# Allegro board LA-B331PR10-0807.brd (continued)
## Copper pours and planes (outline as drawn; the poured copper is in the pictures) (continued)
GND on BOTTOM: 218.68,17.65 222.18,17.65 222.57,18.03 224.32,18.03 224.47,17.87 224.47,15.89 224.17,15.59 222.57,15.59 221.5,14.52 218.48,14.52 218.17,14.83 216.47,14.83 216.32,14.98 216.32,16.35 216.47,16.5 218.45,16.5 218.53,16.58 218.53,17.49
GND on BOTTOM: 193.84,23.13 190.66,23.13 190.41,23.39 190.41,24.48 190.16,24.73 187.49,24.73 187.36,24.86 187.36,26.26 187.23,26.38 183.3,26.38 183.04,26.64 183.04,27.27 183.3,27.53 185.08,27.53 185.2,27.65 185.2,28.92 185.46,29.18 187.49,29.18 187.62,29.05 193.2,29.05 194.35,27.91 194.35,23.64
GND on BOTTOM: 195.84,37.51 193.91,37.51 193.79,37.38 193.79,34.54 193.89,34.43 196.86,34.43 197.19,34.76 197.19,36.16
GND on BOTTOM: 244.05,35.7 244.05,36.24 243.9,36.39 243.22,36.39 243.06,36.24 243.06,35.1 243.22,34.94 243.98,34.94 244.05,35.02 244.05,35.55 244.51,35.55 244.51,35.7
GND on BOTTOM: 235.75,42.88 227.06,42.88 226.68,42.5 226.68,37.09 226.76,37 235.67,37 235.98,37.31 235.98,42.65
GND on BOTTOM: 219.52,31.97 218.37,31.97 218.22,31.82 218.22,31.36 218.6,30.98 218.6,29.84 218.68,29.76 219.52,29.76 219.59,29.84 219.59,31.89
GND on BOTTOM: 216.24,28.31 213.42,28.31 213.35,28.24 213.35,27.25 213.57,27.02 216.32,27.02 216.39,27.09 216.39,28.16
GND on BOTTOM: 278.42,27.48 277.58,28.31 276.9,28.31 276.74,28.16 276.74,27.09 276.9,26.94 276.9,24.05 276.67,23.82 275.33,23.82 275.15,23.64 275.15,20.29 275.28,20.16 276.97,20.16 277.11,20.3 277.11,23.02 277.41,23.31 277.41,23.31 277.98,23.88 277.98,25.49 278.32,25.83 279.69,25.83 280.02,25.49 280.02,24.88 280.55,24.88 280.63,24.96 280.63,25.95 280.55,26.03 279.94,26.03 279.79,26.18 279.79,27.25 279.56,27.48
GND on BOTTOM: 218.53,27.78 218.53,28.69 218.45,28.77 218.37,28.77 218.3,28.69 218.3,27.7 218.37,27.63 218.37,26.03 218.45,25.95 218.68,25.95 218.76,25.87 218.76,24.88 218.83,24.81 218.91,24.81 218.98,24.88 218.98,25.8 219.06,25.87 220.05,25.87 220.13,25.95 220.13,27.55 220.05,27.63 219.44,27.63 219.37,27.7 219.37,28.62 219.29,28.69 219.21,28.69 219.14,28.62 219.14,27.7 219.06,27.63 218.68,27.63
GND on BOTTOM: 271.79,47.33 269.43,47.33 269.35,47.25 269.35,42.75 269.02,42.42 269.02,36.46 269.46,36.02 271.01,36.02 271.26,36.27 271.26,43.32 271.3,43.36 271.3,43.9 271.94,44.54 271.94,47.17
GND on BOTTOM: 209.68,33.27 209.56,33.15 209.56,30.44 209.63,30.37 212.61,30.37 212.85,30.61 212.85,33.12 212.71,33.27
GND on GND1: outline of 113 points within 0.25,0.25 312.25,104.25 ; 1 cut-out
GND on IN1: 142.66,11.51 142.54,11.63 142.54,11.85 142.1,12.29 141.38,12.29 140.96,11.86 139.29,11.86 138.17,12.98 138.17,14.93 137.89,15.21 138.38,15.21 138.38,13.06 139.03,12.41 152.35,12.41 153.02,13.07 153.02,13.38 153.03,13.39 153.03,20.43 152.36,21.1 150.46,21.1 150.38,21.17 150.38,21.65 150.41,21.68 150.67,21.68 150.83,21.51 151.14,21.51 151.33,21.71 151.73,21.71 151.98,21.45 152.08,21.45 152.09,21.46 152.88,21.46 153.55,20.78 153.55,18.33 153.82,18.07 153.82,17.15 154.17,16.8 154.17,16.11 154.34,15.94 154.34,15.74 153.9,15.3 153.9,14.76 154.15,14.51 154.15,14.05 153.67,13.57 153.67,13.42 153.67,13.42 153.67,12.94 152.35,11.63 151.13,11.63 150.64,12.11 149.4,12.11 149.39,12.1 145.12,12.1 144.89,12.32 144.57,12.32 144.51,12.26 144.51,11.78 144.34,11.61 143.79,11.61 143.55,11.86 143.55,12.11 143.47,12.2 143.1,12.2 142.92,12.02 142.92,11.65 142.78,11.51 ; 1 cut-out
GND on IN1: 137.79,15.52 137.79,19.23 137.53,19.49 137.53,20.86 138.3,21.63 141.1,21.63 141.17,21.56 141.17,21.17 141.1,21.1 139.04,21.1 138.38,20.44 138.38,15.52
GND on VCC: 180.61,13.17 180.12,13.66 180.12,26.74 179.21,27.65 177.6,27.65 177.38,27.74 177.16,27.65 169.22,27.65 167.3,25.73 167.3,22.68 159.95,15.33 153.56,15.33 153.01,15.88 153.01,19.99 152.96,20.3 152.83,20.59 152.83,21.05 152.2,21.05 152.06,21.08 151.91,21.09 139.49,21.09 139.34,21.08 139.19,21.05 138.4,21.05 138.4,20.84 137.94,21.3 134.25,21.3 133.39,22.17 133.39,25.09 131.1,27.38 131.1,28.01 129.81,29.3 110,29.3 103.39,35.91 96.92,35.91 95.14,37.69 87.39,37.69 85.36,39.72 71.39,39.72 69.25,41.86 69.25,59.23 209.23,59.23 209.23,58.64 209.23,58.64 209.23,58.5 209.89,56.89 211.5,56.23 246.23,56.23 246.23,54 246.23,52.81 246.23,51.5 246.89,49.89 248.5,49.23 275.5,49.23 277.11,49.89 277.77,51.5 277.77,52.81 277.77,52.81 277.77,103.23 308.56,103.23 308.56,103.23 309.23,103.23 309.23,91.5 309.8,89.99 311.23,89.25 311.23,88.21 311.23,85.77 303.5,85.77 301.89,85.11 301.23,83.5 301.23,36.67 290.89,36.67 287.59,33.37 226.75,33.37 206.56,13.17 ; 1 cut-out
GND on IN2: 142.44,12.39 152.44,12.39 153.04,12.99 153.04,14.49 153.19,14.64 153.8,14.64 153.91,14.53 153.91,10.94 153.34,10.36 145.82,10.36 144.85,11.34 142.48,11.34 142.32,11.49 142.32,12.28
GND on IN2: 153.21,19.3 153.52,19.3 153.61,19.21 153.61,18.39 153.89,18.12 153.89,17.13 154.2,16.82 154.2,15.55 154.02,15.36 153.5,15.36 153.16,15.71 153.16,19.25
GND on IN2: 138.73,21.29 137.99,21.29 137.54,20.85 137.54,19.74 137.63,19.65 138.23,19.65 138.36,19.78 138.36,20.45 138.85,20.94 138.85,21.17
GND on IN3: 153.11,19.27 153.87,19.27 153.96,19.17 153.96,17.58 153.66,17.28 153.07,17.28 153.03,17.32 153.03,19.18
GND on IN3: 138.47,21.3 138.76,21.3 138.89,21.18 138.89,20.95 138.36,20.43 138.36,19.84 138.22,19.69 137.63,19.69 137.56,19.77 137.56,20.47 137.74,20.65 138.2,20.65 138.36,20.8 138.36,21.19
GND on GND2: outline of 115 points within 0.25,0.25 312.25,104.25 ; 1 cut-out
GND on IN4: 137.62,18.37 138.25,18.37 138.36,18.26 138.36,13.11 138.29,13.04 137.86,13.04 137.8,13.09 137.8,13.44 138.13,13.77 138.13,14.54 137.58,15.09 137.58,18.33
GND on IN4: 141.49,12.4 141.57,12.32 141.57,11.9 141.48,11.81 139.61,11.81 139.37,12.05 139.37,12.36 139.41,12.4
GND on IN4: 148.45,12.09 150.79,12.09 151.41,11.46 151.67,11.46 151.74,11.53 151.74,11.7 151.87,11.84 152.62,11.84 152.94,12.16 152.94,12.58 154.52,14.16 154.52,14.63 154.45,14.7 154.1,14.7 154,14.81 154,15.35 154.18,15.54 154.18,16.89 153.85,17.22 153.85,18.35 153.61,18.59 153.61,19.09 153.74,19.22 153.74,19.42 153.65,19.51 153.42,19.51 153.34,19.59 153.34,20.6 152.24,21.7 150.46,21.7 150.37,21.61 150.37,21.17 150.43,21.1 152.35,21.1 153.02,20.43 153.02,13.06 152.36,12.41 148.43,12.41 148.36,12.34 148.36,12.17
GND on GND3: outline of 116 points within 0.25,0.25 312.25,104.25 ; 2 cut-outs
GNDA_CHG on BOTTOM: 244.24,36.24 244.17,36.16 244.17,35.7 244.7,35.7 244.7,35.1 244.17,35.1 244.17,34.73 244.26,34.64 246.04,34.64 246.16,34.76 246.16,36.16 246.09,36.24
GNDA_CHG on IN4: 253.27,38.98 253.27,35.55 252.89,35.17 251.83,35.17 250.61,33.95 250.61,31.89 251.06,31.44 252.59,31.44 253.05,30.98 253.05,28.92 252.74,28.62 250.45,28.62 249.16,27.32 249.16,26.64 249.01,26.48 248.24,26.48 248.02,26.71 248.02,28.47 248.47,28.92 249.46,28.92 250.15,29.61 250.15,30.45 249.85,30.75 247.56,30.75 245.88,29.08 243.22,29.08 242.99,29.3 242.99,31.06 243.06,31.13 244.36,31.13 245.27,32.05 246.95,32.05 247.33,32.43 247.33,34.56 247.1,34.79 245.78,34.79 245.65,34.92 245.65,36.15 245.78,36.28 247.37,36.28 247.79,35.86 250.99,35.86 251.48,36.35 252.63,36.35 252.74,36.47 252.74,37.61 252.51,37.84 252.51,38.91 252.66,39.06 253.2,39.06
VBATT on BOTTOM: 251.45,47.29 251.2,47.04 251.2,43.65 251.44,43.41 256.73,43.41 257.11,43.79 257.11,47.12 256.94,47.29
VDD_1.35V on BOTTOM: 220.13,25.72 219.97,25.72 219.9,25.65 219.9,24.66 220.97,23.59 220.97,22.83 221.04,22.75 223.25,22.75 223.33,22.83 223.33,23.51 223.18,23.67 221.65,23.67 220.13,25.19
+DC_IN on BOTTOM: 255.1,20.24 255.03,20.16 253.27,20.16 252.39,21.05 252.39,22.58 252.5,22.7 253.39,22.7 253.89,23.2 255,23.2 255.1,23.1
+DC_IN on BOTTOM: 280.35,13.21 280.3,13.16 278.14,13.16 278.13,13.17 277.74,13.17 277.57,13.34 277.57,15.83 277.95,16.21 280.26,16.21 280.35,16.13
+DC_IN on BOTTOM: 276.56,6.22 276.67,6.33 276.67,6.88 276.38,7.17 276.38,9.02 276.29,9.11 269.43,9.11 269.12,8.81 269.12,6.53 269.44,6.22
+DC_IN on VCC: 269.13,6.57 268.9,6.8 268.9,17.22 267.73,18.38 253.71,18.38 252.64,19.45 252.64,22.09 253.12,22.57 254.05,22.57 254.18,22.45 272.09,22.45 278.31,16.23 279.7,16.23 279.82,16.11 279.82,11.76 277.28,9.22 277.28,6.68 277.17,6.57
+DCIN on BOTTOM: 250.91,32.05 252.59,32.05 252.97,31.67 255.18,31.67 255.41,31.89 255.41,32.96 255.48,33.04 257.16,33.04 257.24,32.96 257.24,30.98 256.93,30.68 252.74,30.68 251.6,31.82 250.91,31.82 250.84,31.89 250.84,31.97
+INV_PWR_SRC on BOTTOM (solid shape): 263.9,9.54 263.9,8.35 263.85,8.3 262.19,8.3 262.15,8.34 262.15,9.61 262.27,9.72 263.73,9.72
+INV_PWR_SRC on BOTTOM: 242.3,10.54 242.3,9.48 242.85,8.93 243.66,8.93 243.9,9.17 243.9,12.09 244.74,12.93 244.74,13.7 244.65,13.78 244.05,13.78 243.98,13.86 243.98,16.24 243.8,16.41 242.2,16.41 241.84,16.05 241.84,11
+INV_PWR_SRC on IN4: 261.97,9.17 263.35,9.17 263.46,9.06 263.46,7.66 263.26,7.46 242.91,7.46 241.81,8.56 241.81,10.62 242.12,10.94 243.85,10.94 244.1,10.69 244.1,9.97 245.21,8.87 261.82,8.87 261.97,9.02
+LCDVDD on BOTTOM: 256.32,9.62 255.69,9.62 255.56,9.49 255.56,8.35 255.69,8.22 256.32,8.22 256.45,8.35 256.45,9.49
+LCDVDD on BOTTOM: 254.67,12.16 254.8,12.03 256.59,12.03 256.83,12.27 256.83,13.04 255.94,13.92 255.94,15.46 255.81,15.59 255.81,16.28 256.56,17.02 256.56,18.74 256.43,18.86 255.15,18.86 255.12,18.84 255.12,17.41 254.67,16.97
+PBATT on BOTTOM: 247.41,47.44 243.81,47.44 243.61,47.23 243.61,43.59 243.42,43.4 242.83,43.4 242.68,43.25 242.68,42.41 242.76,42.33 245.65,42.33 245.73,42.41 245.73,43.4 246.04,43.71 247.41,43.71 247.71,44.01 247.71,47.13
+PWR_SRC_AC on BOTTOM: 263.64,22.45 261.88,22.45 261.73,22.29 261.73,20.46 261.96,20.24 263.79,20.24 264.09,19.93 264.09,19.63 263.87,19.4 262.04,19.4 261.88,19.25 261.88,18.71 262.04,18.56 262.79,18.56 263.09,18.25 265.12,18.25 265.22,18.36 265.22,19.13 265.01,19.34 265.01,21.53 264.86,21.68 263.94,21.68 263.79,21.84 263.79,22.29
+SDC_IN on BOTTOM: 258.15,22.06 257.39,22.06 257.31,21.99 257.31,18.79 257.47,18.64 261.28,18.64 261.35,18.71 261.35,19.4 261.28,19.47 259.75,19.47 259.52,19.7 259.52,20.08 259.67,20.24 261.28,20.24 261.35,20.31 261.35,21 261.28,21.07 258.61,21.07 258.3,21.38 258.3,21.91
+SIM_PWR on BOTTOM (solid shape): 92.81,6.67 92.81,5.85 93.2,5.45 93.2,4.78 93.04,4.61 92.62,4.61 92.56,4.67 92.56,6.63 92.63,6.71 92.77,6.71
+VCHGR on BOTTOM: 269.05,47.59 257.59,47.59 257.47,47.47 257.47,45.27 257.59,45.15 257.85,45.15 257.85,45.15 258.6,45.15 260.42,43.32 263.79,43.32 264.17,42.94 266.15,42.94 266.23,43.02 266.23,44.62 266.38,44.77 266.84,44.77 266.99,44.62 266.99,43.04 267.12,42.92 269.07,42.92 269.2,43.04 269.2,47.44
B+ on TOP (solid shape): 82.64,21.96 82.64,18.89 82.4,18.65 80.58,18.65 80.08,19.14 80.07,19.14 79.79,19.42 79.79,21.91 80.22,22.34 82.26,22.34
B+ on BOTTOM (solid shape): 278.87,46.59 278.87,46.15 278.78,46.05 278.78,45.29 278.65,45.16 277.76,45.16 277.57,45.35 277.57,46.57 277.76,46.75 278.71,46.75
B+ on BOTTOM (solid shape): 290.97,45.8 290.97,45.03 290.84,44.91 289.95,44.91 289.95,44.91 289.66,44.91 289.58,44.99 289.58,45.73 289.77,45.92 290.85,45.92
B+ on BOTTOM (solid shape): 82.77,20.27 82.77,19.02 82.48,18.73 81.12,18.73 80.9,18.95 80.9,20.24 80.9,20.24 80.9,20.31 81.06,20.46 82.57,20.46
B+ on IN1 (solid shape): 82.21,20.46 82.21,18.99 81.95,18.73 81.05,18.73 80.91,18.87 80.91,20.39 81.06,20.54 82.13,20.54
B+ on IN4 (solid shape): 82.28,20.46 82.28,18.96 82.22,18.89 80.97,18.89 80.91,18.95 80.91,20.54 80.99,20.62 82.13,20.62
B+ on TOP: 208.47,21.46 265.4,21.46 266.72,22.78 266.72,31.63 266.01,32.34 260.92,32.34 259.67,33.58 259.67,40.25 259.78,40.25 260.13,40.61 269.99,40.61 270.88,39.72 278.6,39.72 279.56,38.75 279.56,36.39 279.87,36.09 282.05,36.09 282.31,35.83 282.31,13.51 282.26,13.46 282.26,11.25 281.35,10.34 207.33,10.34 205.89,11.78 204.96,11.78 203.83,10.64 199.71,10.64 195.02,15.33 195.02,24.87 195.39,25.24 204.69,25.24
B+ on BOTTOM: 241.37,16.24 238.4,16.24 238.17,16.01 238.17,12.73 238.25,12.65 241.22,12.65 241.45,12.88 241.45,16.16
B+ on BOTTOM: 267.31,38.37 259.9,38.37 259.67,38.6 259.67,42.72 259.98,43.02 263.64,43.02 264.59,42.07 266.15,42.07 266.23,41.99 266.23,40.39 266.38,40.24 266.84,40.24 266.99,40.39 266.99,42.42 267.27,42.7 268.69,42.7 268.87,42.52 268.87,36.07 268.77,35.97 267.72,35.97 267.57,36.12 267.57,38.11
B+ on BOTTOM: 224.17,20.69 224.17,19.47 224.32,19.32 225.84,19.32 225.99,19.47 225.99,20.69 225.8,20.89 224.36,20.89
B+ on BOTTOM: 195.37,20.16 195.48,20.06 199.85,20.06 200.07,20.28 200.07,32.9 199.91,33.06 196.52,33.06 196.13,32.66 196.13,28.71 195.37,27.96
B+ on BOTTOM: 279.91,21.53 279.02,21.53 278.14,20.65 278.14,19.56 277.84,19.25 277.84,16.64 277.99,16.49 280.46,16.49 280.54,16.57 280.54,17.33 281.01,17.8 281.73,17.8 281.91,17.97 281.91,20.58 281.82,20.66 280.78,20.66
B+_1.05V on BOTTOM (solid shape): 79.47,21.66 82.66,21.66 82.74,21.58 82.74,20.82 82.57,20.65 80.85,20.65 80.67,20.46 80.67,19.37 80.55,19.25 79.59,19.25 79.47,19.38 79.47,19.7 79.21,19.95 77.62,19.95 77.5,20.08 77.5,20.66 76.81,21.35 76.81,22.26 78.87,22.26
BASE_DC_IN_SS on BOTTOM (solid shape): 277.5,19.37 277.5,19 277.41,18.92 276.18,18.92 276.01,18.75 272.73,18.75 272.66,18.82 272.66,19.35 272.82,19.5 277.36,19.5
BATT++ on BOTTOM: 243.37,46.91 243.06,47.21 240.02,47.21 239.86,47.06 239.86,43.78 240.02,43.63 243.22,43.63 243.37,43.78
BATT++ on BOTTOM: 231.01,49.78 239.62,49.78 239.7,49.85 239.7,51.25 239.48,51.47 239.48,51.48 238.64,51.48 238.34,51.78 238.34,52.16 238.19,52.32 236.74,52.32 236.36,52.7 236.36,53.81 236.13,54.04 231.16,54.04 230.78,53.66 230.78,50
BATT++ on IN1: 242.6,43.5 243.16,44.06 243.16,46.37 242.09,47.45 242.09,50.4 240.9,51.58 235.85,51.58 234.07,49.8 234.07,44.09 234.66,43.5
BOOT on BOTTOM: 186.14,21.54 186.14,20.08 186.22,20.01 186.37,20.01 186.45,20.08 186.45,21.26 186.85,21.67 186.93,21.67 186.99,21.73 188.48,21.73 188.56,21.81 188.56,22.93 188.41,23.08 187.71,23.08 187.59,22.96 187.59,22.23 187.51,22.15 187.08,22.15 186.75,21.82 186.42,21.82
BOOT_1.35V on BOTTOM: 218.15,26.87 215.33,26.87 215.1,26.64 215.1,26.03 215.17,25.95 216.09,25.95 216.16,26.03 216.16,26.48 216.24,26.56 217.08,26.56 217.16,26.64 218.15,26.64 218.22,26.71 218.22,26.79
BST_1.05V on BOTTOM (solid shape): 76.09,21.66 76.09,21.18 75.99,21.08 75.52,21.08 75.02,20.58 75.02,20.33 74.89,20.2 74.05,20.2 73.97,20.29 73.97,20.99 74.07,21.09 74.83,21.09 75.21,21.47 75.21,21.49 75.47,21.74 76.01,21.74
BST_1.35V on BOTTOM: 216.09,25.27 215.17,25.27 215.1,25.19 215.1,23.28 215.25,23.13 216.09,23.13 216.16,23.21 216.16,25.19
BST_3V on BOTTOM (solid shape): 284.52,30 284.52,29.18 284.45,29.11 283.88,29.11 283.54,29.46 283.53,29.46 283.45,29.53 282.57,29.53 282.55,29.56 281.53,29.56 281.47,29.62 281.47,29.75 281.53,29.81 283.56,29.81 283.88,30.13 284.39,30.13
BST_5V on BOTTOM (solid shape): 279.5,29.75 279.5,29.62 279.44,29.56 278.43,29.56 278.25,29.38 277.73,29.38 277.34,28.99 277.34,28.61 277.21,28.48 276.58,28.48 276.45,28.61 276.45,29.49 276.52,29.56 277.09,29.56 277.28,29.75 278.36,29.75 278.42,29.81 279.44,29.81
CHAGER_SRC on BOTTOM: 262.11,28.39 266.38,28.39 266.53,28.24 266.53,27.17 266.23,26.87 265.39,26.87 265.16,26.64 265.16,22.06 265.01,21.91 264.17,21.91 264.02,22.06 264.02,22.45 263.79,22.67 261.58,22.67 261.5,22.6 261.5,21.46 261.35,21.3 260.28,21.3 260.21,21.38 260.21,26.18 260.51,26.48 261.81,26.48 261.96,26.64 261.96,28.24
CHG_BTS on BOTTOM: 253.66,34.16 253.68,34.13 253.68,33.19 253.63,33.14 252.23,33.14 252.13,33.04 250.89,33.04 250.86,33.06 250.86,33.19 250.89,33.22 251.93,33.22 252.87,34.16
CHG_BTS_C on BOTTOM: 255.1,34.1 254.34,34.1 254.26,34.03 254.26,31.89 254.34,31.82 255.1,31.82 255.18,31.89 255.18,34.03
CHG_LGATE on BOTTOM: 260.13,33.8 258.91,33.8 258.84,33.72 258.84,32.73 258.91,32.66 260.13,32.66 260.21,32.73 260.21,33.72
CHG_LGATE on BOTTOM: 251.72,34.03 250.91,34.03 250.86,33.98 250.86,33.85 250.89,33.83 252.03,33.83 252.44,34.23 252.44,34.26 252.74,34.56 252.74,34.87 252.59,35.02 252.05,35.02 251.83,34.79 251.83,34.13
CHG_LGATE on IN1: 251.67,34.79 251.67,34.03 251.75,33.95 252.51,33.95 253.5,34.94 253.5,35.17 253.05,35.63 252.51,35.63
CHG_LGATE on IN1: 259.29,33.76 257.92,33.76 257.85,33.69 257.85,32.69 257.92,32.62 259.29,32.62 259.37,32.69 259.37,33.69
CHG_SNUB on BOTTOM: 267.22,34.33 265.39,34.33 265.31,34.26 265.31,32.12 265.39,32.05 267.22,32.05 267.37,32.2 267.37,34.18
CHG_SW on BOTTOM: 250.99,32.43 252.59,32.43 252.97,32.81 253.66,32.81 253.73,32.73 253.73,31.97 253.66,31.89 252.89,31.89 252.59,32.2 250.99,32.2 250.91,32.28 250.91,32.35
CHG_SW on IN4: 260.06,28.24 258.99,28.24 258.91,28.16 258.91,27.25 258.99,27.17 259.98,27.17 260.13,27.32 260.13,28.16
CHG_SW on IN4: 254.57,32.81 253.27,32.81 253.12,32.66 253.12,32.12 253.27,31.97 254.19,31.97 254.65,32.43 254.65,32.73
CHG_SW1 on BOTTOM: 259.92,37.67 259.6,37.34 259.6,34.83 260.25,34.18 260.25,32.92 260.47,32.69 264.63,32.69 265.01,33.08 265.01,34.71 265.31,35.02 267.17,35.02 267.4,35.25 267.4,37.46 267.19,37.67
CHG_UGATE on BOTTOM: 260.68,28.51 261.62,28.51 261.77,28.36 261.77,26.88 261.68,26.8 260.69,26.8 260.61,26.88 260.61,28.44
CHG_UGATE on IN4: 252.13,33.11 252.13,32.66 252.21,32.58 252.82,32.58 253.27,33.04 253.27,33.49 253.2,33.57 252.59,33.57
CHG_UGATE on IN4: 260.74,29.3 260.74,27.48 260.82,27.4 261.58,27.4 261.66,27.48 261.66,29.15 261.43,29.38 260.82,29.38
CPU_B+ on BOTTOM: 195.65,29.11 195.36,28.82 193.82,28.82 193.46,29.18 187.74,29.18 187.62,29.3 185.33,29.3 184.95,28.92 182.41,28.92 182.28,29.05 182.28,29.43 182.41,29.56 182.79,29.56 183.04,29.81 183.04,33.75 183.47,34.18 195.35,34.18 195.65,33.88
DH_1.35V on IN4: 215.17,20.62 215.17,19.4 215.33,19.25 216.16,19.25 216.24,19.32 216.24,20.69 216.16,20.77 215.33,20.77
DL_1.35V on BOTTOM: 216.16,16.5 215.63,16.5 215.56,16.43 215.56,14.83 215.63,14.75 216.16,14.75 216.24,14.83 216.24,16.43
DL_1.35V on BOTTOM: 218.45,25.72 218.3,25.72 217.92,25.34 217.92,23.67 218.07,23.51 218.53,23.51 218.6,23.59 218.6,24.66 218.53,24.73 218.53,25.65
DL_1.35V on IN1: 218.76,24.66 217.84,24.66 217.76,24.58 217.76,22.75 217.84,22.67 218.76,22.67 218.91,22.83 218.91,24.5
DL_1.35V on IN1: 216.85,15.97 215.63,15.97 215.56,15.89 215.56,14.75 215.63,14.67 216.85,14.67 217,14.83 217,15.82
LAGTE on BOTTOM: 187.67,20.85 187.67,20.01 187.74,19.93 188.5,19.93 188.66,20.08 188.66,20.92 188.5,21.07 187.89,21.07
LAGTE on BOTTOM: 182.79,27.53 181.9,27.53 181.65,27.27 181.65,26.38 181.77,26.26 182.79,26.26 182.92,26.38 182.92,27.4
LAGTE on IN1: 182.9,26.95 181.91,26.95 181.84,26.87 181.84,25.68 182.47,25.05 182.73,25.05 182.98,25.3 182.98,26.87
LAGTE on IN1: 188.05,20.01 188.12,19.93 189.11,19.93 189.34,20.16 189.34,21.84 189.27,21.91 188.35,21.91 188.2,21.76 188.2,21.46 188.05,21.3
LDO_3V on BOTTOM (solid shape): 74.78,22.25 75.41,22.25 75.47,22.2 76.04,22.2 76.09,22.15 76.09,21.99 76.04,21.94 75.43,21.94 75.21,21.73 75.05,21.73 74.73,21.41 74.07,21.41 74.07,22.3 74.73,22.3
LG_3V on BOTTOM (solid shape): 286.48,24.16 286.48,23.21 286.42,23.14 285.66,23.14 285.47,23.33 285.47,24.22 285.53,24.29 286.36,24.29
LG_3V on BOTTOM (solid shape): 281.71,28.75 281.85,28.75 282.03,28.57 282.03,27.81 281.87,27.65 281.6,27.65 281.15,28.1 281.15,29.05 281.21,29.11 281.34,29.11
LG_3V on IN1 (solid shape): 282.76,28.49 282.76,27.32 282.61,27.17 281.77,27.17 281.54,27.4 281.54,28.69 281.65,28.8 282.46,28.8
LG_3V on IN1 (solid shape): 286.58,24.8 286.58,23.96 286.47,23.84 285.53,23.84 284.89,24.48 284.89,24.7 285.11,24.92 286.46,24.92
LG_5V on IN4: 274.15,22.02 274.15,20.73 274.22,20.65 274.99,20.65 275.06,20.73 275.06,21.95 274.83,22.17 274.3,22.17
LINE1_L on BOTTOM (solid shape): 96.49,5.32 96.49,4.38 95.2,3.09 95.2,1.8 95.16,1.75 95.06,1.75 95,1.81 95,3.23 95.54,3.77 95.54,4.14 95.94,4.54 95.94,5.38 95.98,5.42 96.39,5.42
LINE1_R on BOTTOM (solid shape): 12,58.1 12,57.74 11.4,57.14 10.62,57.14 10.6,57.16 10.6,57.31 10.7,57.41 10.88,57.41 11.65,58.18 11.92,58.18
LINE1_R on BOTTOM (solid shape): 95.79,5.35 95.79,4.68 95.39,4.27 95.39,3.84 94.8,3.25 94.8,1.82 94.75,1.76 94.63,1.76 94.6,1.79 94.6,3.44 94.95,3.79 94.95,4.18 94.94,4.18 94.94,4.6 95.25,4.91 95.25,5.36 95.29,5.4 95.74,5.4
LX_1.05V on TOP (solid shape): 74.97,19.14 74.84,19.02 73.54,19.02 73.42,19.14 73.42,19.93 73.52,20.03 74.97,20.03
LX_1.05V on TOP (solid shape): 78.01,25.72 78.01,24.55 77.84,24.38 77.05,24.38 76.85,24.58 76.85,25.75 77.02,25.93 77.81,25.93
LX_1.05V on BOTTOM (solid shape): 74.89,19.76 74.89,19.06 74.81,18.98 73.53,18.98 73.44,19.07 73.44,19.98 73.54,20.08 74.57,20.08
LX_1.05V on BOTTOM (solid shape): 82.79,29.9 82.79,28.55 82.7,28.47 82.7,28.46 82.45,28.2 80.93,28.2 80.35,27.63 80.35,26.87 78.01,24.52 78.01,23.33 76.84,23.33 76.84,24.56 76.43,24.97 76.1,24.97 75.53,25.54 75.53,29.47 76.04,29.98 82.7,29.98
LX_3V on BOTTOM (solid shape): 284.9,31.02 284.9,30.38 284.83,30.32 283.82,30.32 283.5,30 281.53,30 281.47,30.07 281.47,30.13 281.53,30.19 282.55,30.19 282.93,30.57 283.31,30.57 283.82,31.08 284.83,31.08
LX_3V on BOTTOM (solid shape): 293.03,25.43 293.03,21.05 292.9,20.92 288.65,20.92 288.17,20.44 285.71,20.44 285.52,20.62 285.52,22.94 285.6,23.02 286.6,23.02 286.67,23.09 286.67,24.6 286.6,24.68 284.08,24.68 283.98,24.78 283.98,25.8 284.06,25.87 292.58,25.87
LX_3V on IN4 (solid shape): 284.62,30.95 284.62,29.46 284.47,29.3 283.7,29.3 283.58,29.43 283.58,30.98 283.73,31.13 284.44,31.13
LX_3V on IN4 (solid shape): 285.35,23.58 286.12,23.58 286.23,23.48 286.23,22.71 286.04,22.51 284.84,22.51 284.19,23.17 282.79,23.17 282.55,23.41 282.55,24.08 282.79,24.32 284.62,24.32
LX_5V on BOTTOM (solid shape): 278.42,30.19 279.44,30.19 279.5,30.13 279.5,30.07 279.44,30 278.42,30 278.29,29.88 277.21,29.88 277.09,29.75 276.52,29.75 276.45,29.81 276.45,30.32 276.52,30.38 278.23,30.38
LX_5V on BOTTOM: 277.89,21.23 277.35,21.23 277.28,21.15 277.28,19.7 277.35,19.63 277.89,19.63 277.96,19.7 277.96,21.15
LX_5V on BOTTOM: 276.74,25.34 268.82,25.34 268.44,24.96 268.44,21.61 268.74,21.3 274.86,21.3 274.98,21.43 274.98,23.71 275.24,23.97 276.67,23.97 276.82,24.12 276.82,25.27
LX_5V on IN1: 273.84,22.14 273.04,22.14 272.92,22.02 272.92,20.55 273.92,19.55 277.87,19.55 277.95,19.63 277.95,20.51 277.84,20.62 274.28,20.62 273.98,20.91 273.98,22
PCH_ON on BOTTOM (solid shape): 78.69,48.62 78.69,47.05 78.62,46.98 78.12,46.98 77.46,47.64 76.41,47.64 76.39,47.67 76.39,47.82 76.41,47.85 77.58,47.85 77.76,48.02 77.76,48.66 77.81,48.71 78.6,48.71
PHASE on TOP (solid shape): 184.97,28.47 184.97,27.75 184.83,27.6 181.85,27.6 181.47,27.22 181.47,26.35 181.69,26.14 183.31,26.14 183.46,25.99 183.46,24.49 183.28,24.31 182.13,24.31 181.14,23.32 181.14,22.32 180.89,22.07 179.61,22.07 179.3,21.76 177.41,21.76 177.16,22.01 177.16,25.41 176.88,25.69 176.88,28.05 177.33,28.5 184.94,28.5
PHASE on BOTTOM: 187.13,21.53 187.13,20.01 187.21,19.93 187.36,19.93 187.44,20.01 187.44,20.93 187.7,21.2 189.62,21.2 189.87,21.45 189.87,22.8 189.71,22.95 188.9,22.95 188.81,22.87 188.81,21.83 188.61,21.63 187.23,21.63
PHASE on BOTTOM: 176.9,28.36 176.9,25.7 177.19,25.41 177.19,25.28 177.44,25.03 179.87,25.03 179.96,24.95 179.96,24.22 179.94,24.21 177.44,24.21 177.18,23.94 177.18,22.01 177.43,21.76 179.28,21.76 179.6,22.08 180.9,22.08 181.14,22.32 181.14,23.46 182.03,24.35 183.3,24.35 183.42,24.48 183.42,26 183.3,26.13 181.72,26.13 181.46,26.38 181.46,27.21 181.9,27.65 184.82,27.65 184.95,27.78 184.95,28.69 184.82,28.82 177.35,28.82
PHASE on IN4: 183.63,28.39 182.71,28.39 182.64,28.31 182.64,27.25 182.71,27.17 183.63,27.17 183.7,27.25 183.7,28.31
PHASE on IN4: 187.06,21 187.13,20.92 187.51,20.92 188.12,21.53 188.12,22.29 188.05,22.37 187.13,22.37 187.06,22.29
SNB_1.05V on BOTTOM (solid shape): 82.81,27.2 82.81,25.37 82.66,25.22 81.75,25.22 81.75,26.05 81.56,26.24 81.54,26.23 80.99,26.23 80.94,26.28 80.94,27.2 81.05,27.32 82.7,27.32
SPK_L+_C on BOTTOM (solid shape): 7.4,56.51 7.4,55.25 7.34,55.2 6.35,55.2 6.06,55.48 6.06,56.39 6.34,56.67 7.23,56.67
SPK_L+_C on BOTTOM (solid shape): 34.26,36.13 34.26,34.7 34.21,34.64 33.22,34.64 33.09,34.77 33.09,36.19 33.15,36.25 34.14,36.25
SPK_L+_C on IN3 (solid shape): 15.98,53.75 15.09,52.86 14.43,52.86 14.15,53.14 14.15,53.79 14.83,54.46 15.27,54.46
SPK_L+_C on IN3 (solid shape): 8.51,56.06 8.51,55.36 8.37,55.23 6.74,55.23 6.57,55.4 6.57,56.23 6.63,56.28 6.63,56.29 6.74,56.4 6.74,56.4 8.17,56.4
SPK_L+_C on IN4 (solid shape): 15.54,53.15 15.54,52.89 15,52.35 14.89,52.35 14.09,53.14 14.09,53.46 14.47,53.83 14.86,53.83
SPK_L+_C on IN4 (solid shape): 33.45,38.59 33.45,37.63 33.85,37.23 33.85,36.09 33.72,35.96 32.89,35.96 32.79,36.07 32.79,37.08 32.41,37.45 32.41,37.61 32.41,37.61 32.41,38.54 32.58,38.72 33.32,38.72
SPK_L+_L on BOTTOM (solid shape): 42.31,7.47 42.31,6.11 42.26,6.06 42.25,6.06 42.25,4.67 41.99,4.41 41.23,4.41 41.14,4.5 41.14,5.53 41.69,6.08 41.69,7.46 41.83,7.6 42.17,7.6
SPK_L+_L on BOTTOM (solid shape): 34.41,34.3 34.41,33.47 33.77,32.84 33.77,31.39 33.77,31.39 33.77,30.92 33.49,30.65 32.62,30.65 32.52,30.75 32.52,30.92 33.07,31.47 33.07,34.42 33.12,34.47 34.23,34.47
SPK_L+_L on IN1 (solid shape): 34.03,30.91 34.03,29.63 33.78,29.38 32.53,30.63 32.53,31.09 32.64,31.19 33.75,31.19
SPK_L+_L on IN1 (solid shape): 42.66,6.4 42.66,5.53 41.6,4.47 41.24,4.47 41.09,4.62 41.09,5.68 41.84,6.42 42.64,6.42
SPK_L-_C on BOTTOM (solid shape): 7.4,54.93 7.4,53.66 7.33,53.6 6.41,53.6 6.18,53.83 6.18,54.9 6.28,54.99 7.33,54.99
SPK_L-_C on BOTTOM (solid shape): 32.82,36.27 32.82,34.64 32.76,34.58 31.79,34.58 31.64,34.73 31.64,36.71 31.71,36.78 32.3,36.78
SPK_L-_C on IN3 (solid shape): 8.59,54.5 8.59,53.8 8.45,53.66 6.82,53.66 6.68,53.8 6.68,54.62 6.89,54.83 8.25,54.83
SPK_L-_C on IN3 (solid shape): 13.88,53.9 13.88,52.77 13.49,52.38 13.08,52.38 12.59,52.87 12.59,54.17 12.65,54.23 13.55,54.23
SPK_L-_C on IN4 (solid shape): 32.14,37.31 32.36,37.09 32.36,36.53 32.26,36.43 31.91,36.43 31.1,37.24 31.1,38.14 31.17,38.21 32.14,38.21
SPK_L-_C on IN4 (solid shape): 13.74,53.11 14.14,52.71 14.14,52.19 13.8,51.86 13.55,51.86 13.48,51.93 13.48,52.12 13.04,52.56 13.04,52.65 13.51,53.12 13.74,53.12
SPK_L-_L on BOTTOM (solid shape): 41.97,8.9 41.97,8.09 41.71,7.82 41.53,7.82 41.31,7.61 41.31,6.16 41.11,5.96 40.83,5.96 40.62,6.17 40.62,8.97 40.73,9.07 41.8,9.07
SPK_L-_L on BOTTOM (solid shape): 32.91,34.32 32.91,33.28 32.78,33.15 32.78,31.35 32.06,30.63 30.82,30.63 30.71,30.75 30.71,31.05 31.66,32 31.85,32 32.09,32.24 32.09,32.87 31.8,33.17 31.8,34.42 31.83,34.45 32.78,34.45
SPK_L-_L on IN1 (solid shape): 32.18,30.99 32.18,29.78 31.99,29.58 31.88,29.58 30.7,30.76 30.7,31.06 30.87,31.22 31.95,31.22
SPK_L-_L on IN1 (solid shape): 41.93,10.02 41.93,7.94 41.85,7.86 41.14,7.86 40.97,8.02 40.97,10.02 41.08,10.13 41.83,10.13
SPK_R+_C on BOTTOM (solid shape): 7.38,53.27 7.38,52.24 7.38,52.01 7.35,51.99 6.21,51.99 6.03,52.17 6.03,53.26 6.17,53.4 7.25,53.4
SPK_R+_C on BOTTOM (solid shape): 36.07,36.95 36.07,35.61 36.05,35.58 35.03,35.58 34.99,35.62 34.99,36.54 35.43,36.98 36.03,36.98
SPK_R+_C on IN3 (solid shape): 7.79,53 7.79,52.21 6.63,52.21 6.53,52.31 6.53,52.9 6.69,53.06 7.72,53.06
SPK_R+_C on IN3 (solid shape): 17.94,52.84 17.94,51.96 17.83,51.85 16.43,51.85 16.32,51.96 16.32,52.84 16.48,53 17.78,53
SPK_R+_C on IN4 (solid shape): 18.3,52.74 18.3,51.14 18.03,50.87 17.64,50.87 17.19,51.31 17.19,52.76 17.42,52.99 18.04,52.99
SPK_R+_C on IN4 (solid shape): 35.94,37.54 35.94,36.08 35.75,35.89 34.91,35.89 34.72,36.08 34.72,36.74 34.83,36.86 34.83,37.52 34.91,37.6 35.87,37.6
SPK_R+_L on BOTTOM (solid shape): 43.36,7.63 43.36,6.05 43.71,5.7 43.71,4.58 43.65,4.52 43.11,4.52 43.1,4.53 42.82,4.53 42.68,4.67 42.68,7.56 42.84,7.71 43.27,7.71
SPK_R+_L on BOTTOM (solid shape): 36.12,35.26 36.12,32.2 35.89,31.96 35.89,31.96 35.43,31.49 35.43,30.27 35.33,30.17 34.38,30.17 34.2,30.35 34.2,31.62 35.47,32.88 35.47,33.85 34.98,34.33 34.98,35.29 35.09,35.4 35.98,35.4
SPK_R+_L on IN1 (solid shape): 35.83,31.05 35.83,29.91 35.63,29.7 35.16,29.7 34.24,30.62 34.24,31.14 34.3,31.21 35.68,31.21
SPK_R+_L on IN1 (solid shape): 44.87,6.46 44.87,5.63 43.79,4.54 43.31,4.54 43.21,4.65 43.21,5.42 44.36,6.58 44.75,6.58
SPK_R-_C on BOTTOM (solid shape): 7.39,51.73 7.39,50.46 7.33,50.4 6.48,50.4 6.03,50.84 6.03,51.58 6.24,51.78 7.34,51.78
SPK_R-_C on BOTTOM (solid shape): 37.59,36.88 37.59,35.6 37.55,35.56 36.5,35.56 36.46,35.61 36.46,36.94 36.52,37 37.47,37
SPK_R-_C on IN3 (solid shape): 18.93,52.78 19.6,52.78 19.71,52.67 19.71,50.63 19.48,50.4 18.78,50.4 18.5,50.68 18.5,52.68 18.65,52.83 18.88,52.83
SPK_R-_C on IN3 (solid shape): 8.29,51.36 8.29,50.53 8.15,50.4 6.69,50.4 6.53,50.55 6.53,50.69 6.53,50.7 6.53,51.4 6.62,51.49 8.16,51.49
SPK_R-_C on IN4 (solid shape): 20.03,52.65 20.03,51.9 19.82,51.69 18.74,51.69 18.56,51.87 18.56,52.74 18.66,52.84 19.83,52.84
SPK_R-_C on IN4 (solid shape): 37.48,37.34 37.48,36.24 37.26,36.02 36.6,36.02 36.38,36.25 36.37,36.25 36.37,37.49 37.32,37.49
SPK_R-_C on IN4 (solid shape): 7.25,51.44 7.25,50.8 7.09,50.64 6.24,50.64 6.07,50.81 6.07,51.31 6.26,51.5 7.19,51.5
SPK_R-_L on BOTTOM (solid shape): 45.77,7.62 45.77,6.1 45.65,5.99 43.84,5.99 43.65,6.18 43.65,7.64 43.79,7.78 45.6,7.78
SPK_R-_L on BOTTOM (solid shape): 37.64,35.21 37.64,34.32 37.54,34.22 37.25,34.22 37.09,34.06 37.09,32.67 37.74,32.01 37.74,30.35 37.65,30.26 36.75,30.26 36.64,30.36 36.64,31.51 36.3,31.85 36.3,32.17 36.3,32.18 36.3,35.28 36.38,35.37 37.48,35.37
SPK_R-_L on IN1 (solid shape): 46.43,7.71 46.43,6.76 46.28,6.61 45.3,6.61 45.14,6.77 45.14,7.8 45.25,7.92 46.23,7.92
SPK_R-_L on IN1 (solid shape): 37.81,31.08 37.81,29.43 37.77,29.39 37.35,29.39 36.52,30.21 36.52,30.66 36.53,30.66 36.53,31.03 36.7,31.2 37.68,31.2
SW_1.5V on BOTTOM (solid shape): 289.19,40.84 289.19,40.09 289.44,39.84 289.98,39.84 290.19,39.64 291.61,39.64 291.8,39.45 291.8,38.23 291.68,38.12 290.15,38.12 289.61,38.65 288.25,38.65 288.05,38.86 288.05,39.8 287.79,40.05 287.64,40.05 287.48,40.22 287.48,41.22 287.54,41.29 288.75,41.29
SW_1.8V on BOTTOM (solid shape): 277,41.1 277,40.34 277.25,40.09 277.79,40.09 277.99,39.89 279.18,39.89 279.33,39.74 279.33,38.37 277.95,38.37 277.42,38.91 276.06,38.91 275.85,39.11 275.85,40.05 275.6,40.31 275.45,40.31 275.29,40.47 275.29,41.48 275.35,41.54 276.56,41.54
SW_1.35V on BOTTOM: 218.15,26.1 217.16,26.1 216.55,25.49 216.55,23.21 216.62,23.13 217.38,23.13 217.46,23.21 217.46,25.04 218.22,25.8 218.22,26.03
SW_1.35V on BOTTOM: 218.22,17.8 215.56,17.8 215.25,18.1 215.25,20.97 215.05,21.18 211.49,21.18 211.36,21.05 211.36,15.11 211.52,14.95 211.52,13.91 211.87,13.56 213.4,13.56 214.29,12.67 215.28,12.67 215.4,12.79 215.4,16.5 215.56,16.65 218.22,16.65 218.3,16.73 218.3,17.72
SW_1.35V on IN4: 216.47,18.1 216.47,17.19 216.55,17.11 217.38,17.11 217.46,17.19 217.46,18.1 217.38,18.18 216.55,18.18
SW_1.35V on IN4: 217.38,24.58 216.55,24.58 216.47,24.5 216.47,23.59 216.55,23.51 217.38,23.51 217.46,23.59 217.46,24.5
UAGTE on BOTTOM: 182.9,29.8 182.9,30.69 182.79,30.81 181.66,30.81 181.61,30.76 181.61,29.71 181.64,29.69 182.79,29.69
UAGTE on IN4: 186.83,20.92 186.9,21 186.9,22.45 186.75,22.6 186.07,22.6 185.99,22.52 185.99,21 186.07,20.92
UAGTE on IN4: 182.38,30.36 181.7,30.36 181.62,30.28 181.62,28.91 181.77,28.76 182.46,28.76 182.69,28.99 182.69,30.05
UG_3V on BOTTOM (solid shape): 282.46,29.38 282.84,29.38 282.92,29.3 282.92,28.77 282.84,28.69 282.53,28.69 282.22,29.01 281.7,29.01 281.47,29.24 281.47,29.37 281.53,29.43 282.41,29.43
UG_3V on IN4: 282.43,29.46 282.38,29.41 282.38,28.14 282.53,27.98 283.3,27.98 283.37,28.06 283.37,29.41 283.32,29.46
UG_3V on IN4: 283.21,22.14 281.84,22.14 281.56,22.42 281.56,22.95 281.79,23.18 282.28,23.18 282.48,22.98 283.21,22.98 283.29,22.9 283.29,22.22
UG_5V on BOTTOM (solid shape): 279.5,29.37 279.5,29.24 279.03,28.77 279.03,28.54 278.98,28.49 278.12,28.49 277.99,28.62 277.99,29.08 278.14,29.23 278.34,29.23 278.55,29.43 279.44,29.43
UG_5V on BOTTOM: 277.23,21.76 277.23,21.4 277.28,21.35 278.57,21.35 278.67,21.46 278.75,21.46 279.03,21.73 279.03,22.01 278.93,22.12 278.32,22.12 278.06,21.86 277.33,21.86
UG_5V on IN1: 278.76,29.02 278.08,29.02 277.85,28.79 277.85,27.59 278.05,27.39 278.66,27.39 279.03,27.75 279.03,28.87 278.9,29.01 278.78,29.01
UG_5V on IN1: 278.98,21.36 279.07,21.44 279.07,22.96 278.98,23.04 277.84,23.04 277.81,23.01 277.81,21.39 277.84,21.36
VS_EN on BOTTOM (solid shape): 78.15,46.69 78.59,46.69 78.64,46.64 78.64,45.03 78.55,44.94 78.03,44.94 77.93,45.04 77.93,46.41 77.51,46.83 76.44,46.83 76.39,46.88 76.39,46.98 76.44,47.03 77.81,47.03
N22841841 on BOTTOM (solid shape): 75.07,48.86 75.07,48.13 74.99,48.05 73.34,48.05 73.19,47.9 72.53,47.9 72.46,47.97 72.46,48.97 72.55,49.07 74.86,49.07
N41500729 on BOTTOM (solid shape): 86.29,33.29 86.29,32.3 86.68,31.92 86.68,30.32 86.57,30.22 85.53,30.22 85,30.75 85,33.33 85.1,33.43 86.15,33.43
N43454028 on BOTTOM: 232.4,28.72 231.48,28.72 230.95,29.25 229.88,29.25 229.8,29.18 229.8,28.49 229.96,28.34 230.64,28.34 231.13,27.86 232.4,27.86 232.47,27.93 232.47,28.64
N44372336 on BOTTOM (solid shape): 297.91,63.2 297.91,61.37 297.86,61.32 297.24,61.32 296.25,62.31 296.25,63.64 296.45,63.85 297.27,63.85
N47519532 on BOTTOM: 251.05,18.89 254.29,18.89 254.42,18.76 254.42,17.49 254.29,17.37 251,17.37 250.91,17.45 250.91,18.75
N48029100 on BOTTOM: 218.04,14.52 217,14.52 216.85,14.37 216.85,12.84 217,12.69 219.44,12.69 219.77,13.02 219.77,14.17 219.72,14.22 218.35,14.22
N48096331 on BOTTOM (solid shape): 285.85,31.02 285.85,29.18 285.79,29.11 285.21,29.11 285.15,29.18 285.15,31.02 285.21,31.08 285.79,31.08
N48096357 on BOTTOM (solid shape): 285.53,28.61 285.53,26.7 285.47,26.64 284.07,26.64 284.01,26.7 284.01,27.4 284.07,27.46 284.64,27.46 284.83,27.65 284.83,28.67 285.47,28.67
N48096365 on BOTTOM (solid shape): 276.13,28.22 276.13,27.27 276.32,27.08 276.52,27.08 276.71,26.89 276.71,26.07 276.64,26 275.31,26 275.18,26.13 275.18,28.1 275.31,28.23 276.13,28.23
N48096452 on BOTTOM (solid shape): 276.2,30.32 276.2,28.92 275.81,28.53 275.19,28.53 275.12,28.61 275.12,29.88 275.63,30.38 276.13,30.38
N49571039 on BOTTOM (solid shape): 73.31,21.05 73.31,19.03 73.26,18.98 72.58,18.98 72.54,19.03 72.54,20.96 72.67,21.09 73.26,21.09
N50198050 on BOTTOM (solid shape): 99.76,26.51 99.76,21.1 99.63,20.97 98.69,20.97 98.46,21.2 98.46,24.7 98.63,24.87 98.63,26.57 98.72,26.66 99.6,26.66
N50817741 on BOTTOM: 255.81,24.13 255.26,23.57 255.26,23.21 255.18,23.13 255.18,19.78 255.33,19.63 257.08,19.63 257.16,19.7 257.16,26.49 257.05,26.6 256.63,26.6 256.38,26.35 256.05,26.35 255.81,26.1
N51581707 on BOTTOM: 241.02,19.16 242.13,19.16 242.21,19.07 242.21,18.06 242.12,17.97 241.28,17.97 241.07,17.76 240.65,17.76 240.63,17.74 240.63,16.82 240.54,16.73 239.79,16.73 239.76,16.75 239.76,18.22 239.9,18.35 240.79,18.35 240.94,18.5 240.94,19.07
N51582271 on BOTTOM (solid shape): 11.58,40.48 11.58,39.96 11.57,39.95 10.83,39.95 10.67,40.11 9.4,40.11 9.22,39.93 8.06,39.93 7.51,39.38 6.94,39.38 6.74,39.18 6.74,38.79 6.63,38.67 6.03,38.67 5.92,38.79 5.92,39.86 5.99,39.93 7.49,39.93 8.11,40.54 11.52,40.54
N51582977 on BOTTOM (solid shape): 75.12,46.5 75.12,44.39 75.02,44.29 74.13,44.29 73.92,44.49 73.92,46.53 74.03,46.63 74.99,46.63
N51584481 on BOTTOM (solid shape): 300.84,63.85 300.84,63.14 300.67,62.97 300.28,62.97 300.04,62.73 300.04,61.43 299.91,61.31 299.38,61.31 299.32,61.36 299.32,62.96 299.69,63.33 299.69,63.81 299.79,63.91 300.78,63.91
N51589797 on BOTTOM (solid shape): 36.66,45.66 36.66,44.62 34.64,42.6 34.05,42.6 33.94,42.7 33.94,43.57 34.75,44.38 34.75,45.74 34.8,45.8 36.53,45.8
N51592304 on BOTTOM: 232.4,32.38 231.56,32.38 231.37,32.18 230.07,32.18 229.73,31.84 229.73,30.7 229.8,30.62 230.57,30.62 231.02,31.08 232.28,31.08 232.43,31.23 232.43,32.35
N51597050 on BOTTOM (solid shape): 32.59,45.39 32.59,42.69 32.5,42.59 32.02,42.59 31.62,42.99 31.48,42.99 30.54,43.93 30.54,45.43 30.73,45.62 32.36,45.62
N51600655 on BOTTOM (solid shape): 15.53,36.97 15.61,36.97 15.73,36.85 15.73,36.17 15.62,36.06 14.86,36.06 14.65,36.26 13,36.26 12.86,36.4 12.86,36.57 12.87,36.57 12.87,36.92 12.94,36.99 15.52,36.99
N51600691 on BOTTOM (solid shape): 15.78,40.21 15.78,39.5 15.66,39.38 15.01,39.38 14.04,38.41 13.68,38.41 13.65,38.38 12.94,38.38 12.85,38.47 12.85,39.21 12.96,39.32 13.54,39.32 14.6,40.39 15.61,40.39
N52122807 on BOTTOM: 249.2,46.94 248.05,46.94 247.94,46.83 247.94,45.15 248.09,45 249.24,45 249.31,44.92 249.31,44.39 249.16,44.24 248.4,44.24 247.52,43.36 246.99,43.36 246.84,43.21 246.84,42.6 246.99,42.45 249.65,42.45 249.73,42.52 249.73,43.18 251,44.45 251,46.14 250.88,46.26 249.5,46.26 249.35,46.41 249.35,46.79
N52128481 on BOTTOM (solid shape): 277.59,18.46 277.59,16.05 277.42,15.88 277.42,15.71 277.38,15.64 277.31,15.61 277.28,15.61 276.69,15.61 276.36,15.28 276.69,14.95 277.28,14.95 277.31,14.95 277.38,14.93 277.42,14.85 277.42,13.25 277.28,13.11 275.29,13.11 275.21,13.2 275.21,16.29 274.66,16.83 274.25,16.83 274.11,16.97 274.11,18.25 274.27,18.41 276.12,18.41 276.35,18.64 277.41,18.64
N53141348 on BOTTOM (solid shape): 14.44,44.02 14.44,42.79 13.57,41.93 12.96,41.93 12.81,42.08 12.81,42.58 11.93,43.47 11.93,43.77 12.23,44.07 14.39,44.07
N53478114 on BOTTOM: 80.66,13.4 79.91,13.4 79.83,13.32 79.83,11.16 79.89,11.09 80.78,11.09 80.83,11.14 80.83,11.9 80.71,12.03 80.71,13.35
N53764974 on BOTTOM: 186.98,26.26 184.95,26.26 184.82,26.13 184.82,24.6 184.95,24.48 186.98,24.48 187.11,24.6 187.11,26.13
N54019866 on BOTTOM (solid shape): 298.08,50.41 298.08,49.64 299.15,48.58 299.15,47.92 299.12,47.9 298.31,47.9 297.54,48.66 297.54,48.66 297.44,48.77 297.15,48.77 297.03,48.88 297.03,50.34 297.21,50.52 297.98,50.52
N54825153 on BOTTOM (solid shape): 79.22,40.85 79.22,40 79.15,39.93 77.13,39.93 77.1,39.96 77.1,40.64 77.17,40.71 78.23,40.71 78.42,40.9 79.17,40.9
N93297423 on BOTTOM: 241.93,10.48 241.09,10.48 241.04,10.43 241.04,8.4 241.86,7.59 242.54,7.59 242.71,7.75 242.71,8.43 242.03,9.1 242.03,10.38
N115444061 on BOTTOM: 189.99,24.39 187.6,24.39 187.55,24.34 187.55,23.62 187.61,23.55 189.99,23.55 190.07,23.63 190.07,24.31

Small or netless copper shapes (teardrops, artwork), in the pictures only: 11 on TOP, 142 on BOTTOM, 1 on IN1, 42 on VCC, 14 on IN4, 1 on IN2, 2 on IN3

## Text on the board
Ref Des/Silkscreen Bottom: M2X2 | H9 | CH-B | CH-A | H-4GB/8GB | M-4GB | M-8GB | H8 | B | A | SSD CARD | WWLAN/WGIG CARD | HCA/WWAN CARD
User.Comments: LA-B331P | 2015-08-07 | 2014-08-07 | Moopi | ZAU70 | 1.0(A00)
COMPVAL_TYPE_BOTTOM: trace Width | Width/space | Single 50ohm | 4.8mil | 6.5mil | 3.8mil | 2.6mil | 5.4 / 4 | 7 / 4 | 3.8 / 4 | 2.6 / 2.7 | 3.8 / 3.2 | 2.6 / 3.3 | 1_0mm_2+6+2(50ohm 3.8mil 2.6mil) (Top GND IN1 G-V IN2 IN3 G-V IN4 GND Bot)-131120 | L1-TOP | L2-GND1 | L3-IN1 | L4-VCC | L5-IN2 | L6-IN3 | L7-GND2 | L8-IN4 | L9-GND3 | L10-BOT | LAYER | NAME | STACKUP: 10 LAYER | 37 ohm | 50 ohm | 65 ohm | THICKNESS=1.0mm | 85 ohm | 88 ohm
USER_PART_NUM_BOTTOM: FIGURE | SIZE | 8.0 | 20.0 | 47.0 | 146.0 | 181.0 | 43.0 | 63.0 | 157.0 | 69.0x20.0 | 197.0x157.0 | DRILL CHART: TOP to BOTTOM | ALL UNITS ARE IN MILS | TOLERANCE | +3.0/-3.0 | +2.0/-2.0 | PLATED | NON-PLATED | QTY | 2310 | 33 | 2 | 1 | 4 | 3
DEVICE_TYPE_BOTTOM: FIGURE | SIZE | 8.0 | DRILL CHART: IN1 to IN4 | ALL UNITS ARE IN MILS | TOLERANCE | +3.0/-3.0 | PLATED | QTY | 1281
PAGE_OUTLINE: FIGURE | SIZE | 4.0 | DRILL CHART: IN4 to BOTTOM | ALL UNITS ARE IN MILS | TOLERANCE | +1.0/-1.0 | PLATED | QTY | 1813
User.6: FIGURE | SIZE | 4.0 | DRILL CHART: GND3 to BOTTOM | ALL UNITS ARE IN MILS | TOLERANCE | +1.0/-1.0 | PLATED | QTY | 1366
User.7: FIGURE | SIZE | 4.0 | DRILL CHART: GND1 to IN1 | ALL UNITS ARE IN MILS | TOLERANCE | +1.0/-1.0 | PLATED | QTY | 92
User.8: FIGURE | SIZE | 4.0 | DRILL CHART: IN4 to GND3 | ALL UNITS ARE IN MILS | TOLERANCE | +1.0/-1.0 | PLATED | QTY | 85
User.9: FIGURE | SIZE | 4.0 | DRILL CHART: TOP to IN1 | ALL UNITS ARE IN MILS | TOLERANCE | +1.0/-1.0 | PLATED | QTY | 178
User.10: FIGURE | SIZE | 4.0 | DRILL CHART: TOP to GND1 | ALL UNITS ARE IN MILS | TOLERANCE | +1.0/-1.0 | PLATED | QTY | 85
